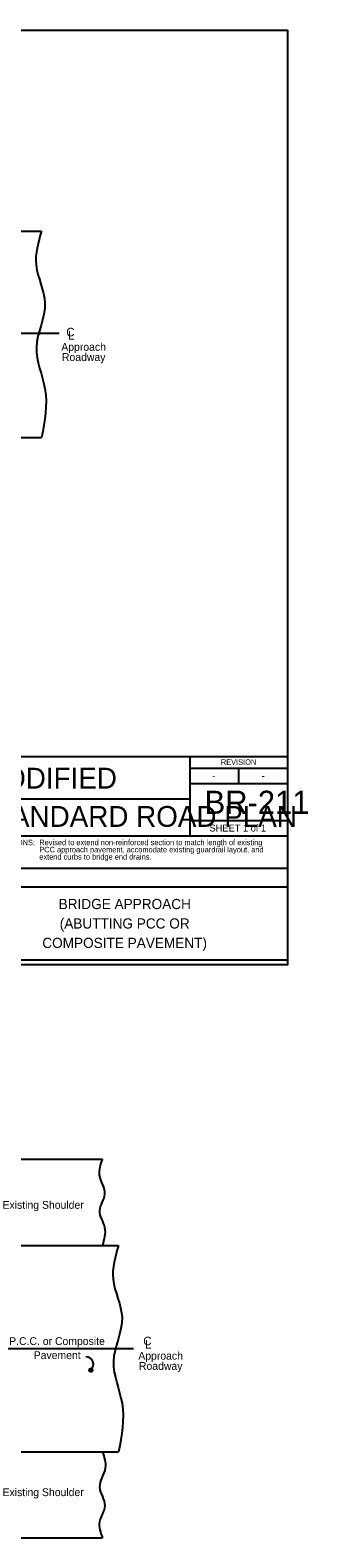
# Model space of a CAD drawing. Extents: x 5546 to 81668, y 3174 to 15999.
# Drawn here: x 24175 to 24776, y 12542 to 15800 of the extents above; entities that cross this region are included whole.
import ezdxf

# ---------------------------------------------------------------- set-up
doc = ezdxf.new("R2010")
doc.units = 0
for name, color, linetype in [('Level 61', 7, 'Continuous'), ('PS_BOLT', 7, 'Continuous'), ('PS_DIM', 7, 'Continuous'), ('tdCoLegendTitle', 7, 'Continuous'), ('tdCoShieldUsRte', 7, 'Continuous')]:
    doc.layers.add(name, color=color, linetype=linetype)

msp = doc.modelspace()

# ---------------------------------------------------------------- linework, layer by layer
at = {"layer": 'Level 61'}
msp.add_lwpolyline([(21596.3, 15800.4), (24731.3, 15800.4), (24731.3, 13780.4), (21596.3, 13780.4)], close=True, dxfattribs=at)
at = {"layer": 'PS_BOLT'}
msp.add_arc((24295.2, 12916.8), 16.5, 311.309, 90, dxfattribs=at)
at = {"layer": 'PS_DIM'}
for p, q in [((23903.1, 15366.2), (24199.5, 15366.2)), ((22356.3, 15145.3), (24237.5, 15145.3)), ((23903.1, 14920), (24199.5, 14920)), ((24069.8, 13360), (24331.1, 13360)), ((24069.8, 13174), (24366.1, 13174)), ((22039.6, 12950.9), (24398.5, 12950.9)), ((24069.8, 12727.8), (24366.1, 12727.8)), ((24069.8, 12541.8), (24331.1, 12541.8))]:
    msp.add_line(p, q, dxfattribs=at)
msp.add_lwpolyline([(24305.8, 12901), (24307, 12901.6), (24308.9, 12902.2), (24309.3, 12904.1), (24309, 12905.8), (24307.8, 12907.4), (24306, 12907.2), (24304.1, 12906.9), (24303.2, 12905.4), (24303, 12903.8), (24304.1, 12901.7), (24305.5, 12901.5), (24307.4, 12902), (24309, 12903.2), (24308.9, 12905), (24307.7, 12906.5), (24306, 12906.7), (24304.1, 12906.3), (24303.8, 12905.2), (24303.4, 12903.9), (24304.3, 12902.4), (24305.7, 12902.4), (24307.3, 12902.7), (24308.4, 12903.5), (24307.9, 12905.1), (24306.7, 12906), (24305.1, 12906.1), (24304.7, 12905.2), (24304.2, 12904.3), (24304.9, 12903), (24306.1, 12902.7), (24307.2, 12903.3), (24307.2, 12904.5), (24306.7, 12905.3), (24305.6, 12905.6), (24305.1, 12905.1), (24304.8, 12904.5), (24305.4, 12903.6), (24306.1, 12903.4), (24306.8, 12903.8), (24306.7, 12904.4), (24306.2, 12904.9), (24305.4, 12904.8), (24305.4, 12904.3), (24306.1, 12904)], dxfattribs=at)
msp.add_circle((24306.1, 12904.4), 3.62, dxfattribs=at)
for points in [[(24199.5, 15366.2), (24187.5, 15293.1), (24206.9, 15210.2), (24188.3, 15114.8), (24206.9, 15024.9), (24199.5, 14920)], [(24331.1, 13360), (24324.2, 13325.6), (24336, 13284.7), (24324.6, 13249), (24336, 13212.2), (24331.1, 13174)], [(24366.1, 13174), (24354.2, 13100.9), (24373.6, 13018), (24355, 12922.6), (24373.6, 12832.7), (24366.1, 12727.8)], [(24331.1, 12727.8), (24337.2, 12692.9), (24325.1, 12650.9), (24336.2, 12610.9), (24324.8, 12576.3), (24331.1, 12541.8)]]:
    msp.add_spline(points, degree=3, dxfattribs=at)
at = {"layer": 'tdCoLegendTitle'}
for p, q in [((24520.4, 14230.4), (24520.4, 14139.1)), ((24520.4, 14205.5), (24731.3, 14205.5)), ((24625.9, 14205.5), (24625.9, 14172.3)), ((24520.4, 14172.3), (24731.3, 14172.3)), ((24043.3, 14139.1), (24520.4, 14139.1)), ((24520.4, 14139.1), (24520.4, 14059)), ((24731.3, 14091.2), (24520.4, 14091.2)), ((24043.3, 14059), (24731.3, 14059)), ((24043.3, 13989), (24731.3, 13989)), ((24043.3, 13949), (24731.3, 13949)), ((24043.3, 13949), (24731.3, 13949))]:
    msp.add_line(p, q, dxfattribs=at)
msp.add_lwpolyline([(24043.3, 14230.4), (24731.3, 14230.4), (24731.3, 13790.4), (24043.3, 13790.4)], close=True, dxfattribs=at)

# ---------------------------------------------------------------- texts
at = {"layer": 'PS_BOLT'}
for s, height, p in [('C', 18.5, (24253, 15138.5)), ('Approach', 16.88, (24242.2, 15107.4)), ('L', 18.5, (24256.9, 15131.4)), ('Roadway', 16.88, (24243.6, 15085.4)), ('Existing Shoulder', 16.884, (24115.1, 13253)), ('P.C.C. or Composite', 16.884, (24129.4, 12958.6)), ('C', 18.5, (24419.6, 12958)), ('L', 18.5, (24423.5, 12950.9)), ('Pavement', 16.88, (24182.5, 12928.2)), ('Approach', 16.88, (24408.8, 12926.9)), ('Roadway', 16.88, (24410.2, 12904.9)), ('Existing Shoulder', 16.884, (24115.1, 12632))]:
    msp.add_text(s, height=height, dxfattribs=at).set_placement(p)
at = {"layer": 'tdCoLegendTitle'}
for s, height, p in [('REVISION', 12, (24587.4, 14212.5)), ('-', 15, (24568.9, 14181)), ('-', 15, (24675.4, 14181.5)), ('BR-211', 50, (24552.3, 14106.6)), ('STANDARD ROAD PLAN', 45.001, (24056.4, 14078.5)), ('SHEET 1 of 1', 15, (24562.8, 14068.4)), ('Revised to extend non-reinforced section to match length of existing ', 12, (24194.6, 14038.8)), ('extend curbs to bridge end drains.', 12, (24194.6, 14007.7)), ('PCC approach pavement, accomodate existing guardrail layout, and ', 12, (24194.6, 14023.3)), ('BRIDGE APPROACH', 22, (24236.5, 13900.7)), ('(ABUTTING PCC OR', 22, (24238.8, 13858.7)), ('COMPOSITE PAVEMENT)', 22, (24201.1, 13816.7))]:
    msp.add_text(s, height=height, dxfattribs=at).set_placement(p)
at = {"layer": 'tdCoShieldUsRte'}
for s, height, p in [('MODIFIED', 45, (24068.4, 14161.2)), ('MODIFICATIONS:', 12, (24053.3, 14038.7))]:
    msp.add_text(s, height=height, dxfattribs=at).set_placement(p)

doc.saveas('drawing.dxf')
